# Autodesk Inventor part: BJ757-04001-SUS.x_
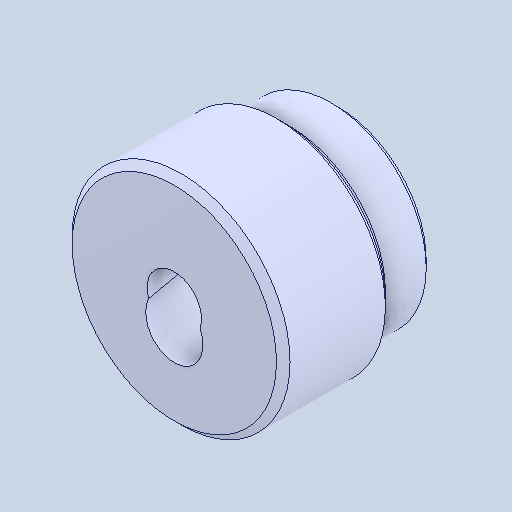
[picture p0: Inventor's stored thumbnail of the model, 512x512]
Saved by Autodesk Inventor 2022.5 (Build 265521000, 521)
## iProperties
Created: 2024-05
Part Number: BJ757-04001-SUS.x_
Material: 一般
Document SubType Name: Modeling
Designer: ImaoCorp
Density: 1 g/cm^3
Appearance: 既定
Author: ImaoCorp
Sending System: SOLIDWORKS 2022-2022290
MC: AMD64
MC_MODEL: Intel64 Family 6 Model 60 Stepping 3, GenuineIntel
OS: Windows_NT
FRU: Parasolid Version 33.1, build 260,  4-25-2022
FORMAT: text
GUISE: transmit
KEY: FILEBJ757-04001-SUS.x_t
DATE: Tue May 21 08:47:14 2024
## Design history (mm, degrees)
feature "Base1"
node "ソリッド1"
